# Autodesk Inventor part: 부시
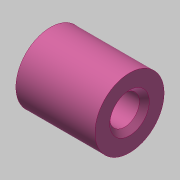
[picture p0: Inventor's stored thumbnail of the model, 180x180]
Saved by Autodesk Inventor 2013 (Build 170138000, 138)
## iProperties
Created: 2019-02
Part Number: 부시
Material: 스테인리스강
Document SubType Name: Modeling
Designer: mduedu
Density: 1 g/cm^3
Author: mduedu
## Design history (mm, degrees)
sketch "스케치1"
  geometry: C1 r 3 at (0, 0); C2 r 7 at (0, 0); 1 further point
  constraints: 2 centre point, 2 coincident
  dimensions: "d0" = 6 diameter of C1; "d1" = 14 diameter of C2
extrude "돌출1" new body sketch "스케치1" stored distance "d2" = 16; taper "d3" = 0 deg
chamfer "모따기1" distance "d4" = 1; stored, may be unused: second distance "d5" = 2, angle "d6" = 45 deg
node "솔리드1"
